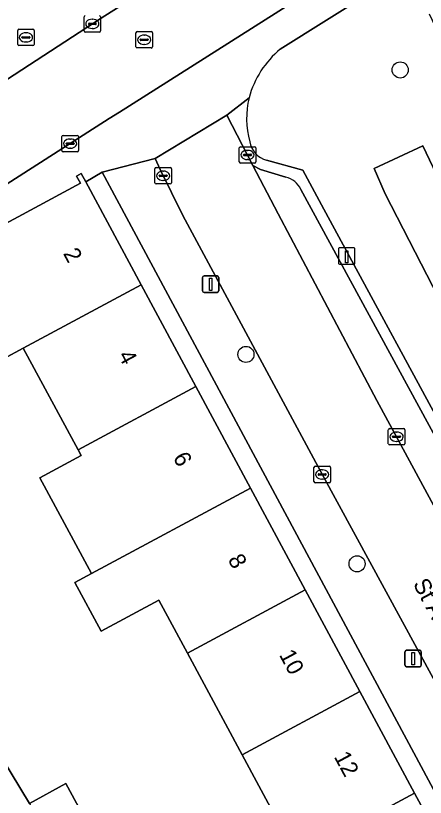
# Model space of a CAD drawing. Extents: x 162523 to 163266, y 381230 to 382050.
# Drawn here: x 162740.82 to 162765.64, y 381862.71 to 381910.12 of the extents above; entities that cross this region are included whole.
import ezdxf

# ---------------------------------------------------------------- set-up
doc = ezdxf.new("R2010")
doc.units = 0
for name, color, linetype in [('IMGEO_Boom', 7, 'Continuous'), ('IMGEO_Brandkraan', 7, 'Continuous'), ('IMGEO_Erf', 7, 'Continuous'), ('IMGEO_Groenvoorziening', 7, 'Continuous'), ('IMGEO_Kolk', 7, 'Continuous'), ('IMGEO_Laadpaal', 7, 'Continuous'), ('IMGEO_Lichtmast', 7, 'Continuous'), ('IMGEO_Openbare_ruimte_label', 7, 'Continuous'), ('IMGEO_Pand', 7, 'Continuous'), ('IMGEO_Pand_nummerreeks', 7, 'Continuous'), ('IMGEO_Parkeervlak_open', 7, 'Continuous'), ('IMGEO_Rijbaan_lokaal_open', 7, 'Continuous'), ('IMGEO_Rioolput', 7, 'Continuous'), ('IMGEO_Voetpad_gesloten', 7, 'Continuous'), ('IMGEO_Voetpad_open', 7, 'Continuous')]:
    doc.layers.add(name, color=color, linetype=linetype)

msp = doc.modelspace()

# ---------------------------------------------------------------- linework, layer by layer
at = {"layer": 'IMGEO_Boom'}
for centre in [(162764.122, 381906.826), (162754.771, 381889.574), (162761.508, 381876.876)]:
    msp.add_circle(centre, 0.489, dxfattribs=at)
at = {"layer": 'IMGEO_Brandkraan'}
for p, q in [((162740.939, 381908.375), (162740.939, 381909.227)), ((162741.014, 381909.301), (162741.866, 381909.301)), ((162741.427, 381909.081), (162741.452, 381909.081)), ((162741.94, 381909.227), (162741.94, 381908.375)), ((162741.198, 381908.795), (162741.198, 381908.807)), ((162741.636, 381908.758), (162741.238, 381908.758)), ((162741.241, 381908.844), (162741.639, 381908.844)), ((162741.45, 381908.521), (162741.425, 381908.521)), ((162741.682, 381908.807), (162741.682, 381908.795)), ((162741.866, 381908.301), (162741.014, 381908.301))]:
    msp.add_line(p, q, dxfattribs=at)
for points in [[(162740.939, 381908.375), (162740.939, 381909.227)], [(162741.014, 381909.301), (162741.866, 381909.301)], [(162741.94, 381909.227), (162741.94, 381908.375)], [(162741.866, 381908.301), (162741.014, 381908.301)]]:
    msp.add_lwpolyline(points, dxfattribs=at)
for centre, radius, start, end in [((162741.016, 381909.225), 0.0765, 91.552, 178.448), ((162741.016, 381909.225), 0.0765, 91.552, 178.448), ((162741.864, 381909.225), 0.0765, 1.552, 88.448), ((162741.864, 381909.225), 0.0765, 1.552, 88.448), ((162741.238, 381908.804), 0.0403, 85.8775, 175.7526), ((162741.235, 381908.794), 0.0366, 178.938, 274.7102), ((162741.639, 381908.801), 0.043, 264.8664, 352.4533), ((162741.643, 381908.806), 0.0386, 1.7309, 96.639), ((162741.016, 381908.377), 0.0765, 181.552, 268.448), ((162741.016, 381908.377), 0.0765, 181.552, 268.448), ((162741.864, 381908.377), 0.0765, 271.552, 358.448), ((162741.864, 381908.377), 0.0765, 271.552, 358.448)]:
    msp.add_arc(centre, radius, start, end, dxfattribs=at)
for centre, major_axis, ratio, start_param, end_param in [((162741.426, 381908.801), (-0.387, 0.002), 0.722429, 4.712389, 7.853982), ((162741.451, 381908.801), (-0.39, 0.002), 0.717154, 1.570796, 4.712389)]:
    msp.add_ellipse(centre, major_axis=major_axis, ratio=ratio, start_param=start_param, end_param=end_param, dxfattribs=at)
at = {"layer": 'IMGEO_Erf'}
msp.add_lwpolyline([(162745.066, 381900.034), (162748.419, 381893.798), (162751.735, 381887.632), (162755.05, 381881.467), (162758.365, 381875.302), (162761.68, 381869.137), (162764.996, 381862.972), (162768.311, 381856.807), (162771.626, 381850.642), (162774.941, 381844.476), (162778.257, 381838.311), (162781.572, 381832.146), (162784.887, 381825.982), (162788.202, 381819.816), (162791.67, 381813.368), (162792.763, 381813.94), (162777.492, 381842.022), (162746.054, 381900.628)], close=True, dxfattribs=at)
msp.add_lwpolyline([(162757.857, 381859.135), (162754.542, 381865.3), (162751.226, 381871.465), (162749.501, 381874.674), (162745.998, 381872.79), (162744.408, 381875.746), (162745.415, 381876.288), (162742.291, 381882.096), (162744.788, 381883.439), (162744.596, 381883.796), (162741.28, 381889.961), (162738.872, 381888.666), (162735.626, 381894.706), (162728.869, 381890.045), (162730.638, 381887.218), (162727.784, 381885.433), (162729.455, 381882.762), (162731.926, 381884.308), (162733.354, 381881.705), (162735.225, 381878.293), (162732.802, 381876.964), (162741.663, 381862.35), (162743.847, 381863.545), (162745.536, 381860.46)], dxfattribs=at)
at = {"layer": 'IMGEO_Groenvoorziening'}
for points in [[(162762.462, 381911.617), (162756.853, 381908.091)], [(162756.019, 381901.355), (162758.227, 381900.744), (162759.496, 381898.373), (162768.087, 381882.528), (162776.948, 381886.694), (162771.409, 381898.579), (162765.889, 381910.215)]]:
    msp.add_lwpolyline(points, dxfattribs=at)
for points in [[(162767.915, 381890.155), (162771.041, 381891.621), (162766.734, 381899.634), (162765.498, 381902.226), (162762.536, 381900.85), (162763.217, 381899.313)], [(162765.498, 381902.226), (162766.734, 381899.634), (162771.041, 381891.621), (162767.915, 381890.155), (162763.217, 381899.313), (162762.536, 381900.85)]]:
    msp.add_lwpolyline(points, close=True, dxfattribs=at)
for centre, radius, start, end in [((162760.626, 381903.59), 5.874, 129.9718, 164.6541), ((162760.088, 381903.884), 5.278, 166.191, 195.4833), ((162756.365, 381902.692), 1.381, 189.0384, 255.4988)]:
    msp.add_arc(centre, radius, start, end, dxfattribs=at)
at = {"layer": 'IMGEO_Kolk'}
for p, q in [((162744.962, 381909.193), (162744.962, 381910.045)), ((162745.963, 381910.045), (162745.963, 381909.193)), ((162745.221, 381909.613), (162745.221, 381909.625)), ((162745.659, 381909.576), (162745.261, 381909.576)), ((162745.264, 381909.662), (162745.662, 381909.662)), ((162745.45, 381909.899), (162745.475, 381909.899)), ((162745.705, 381909.625), (162745.705, 381909.613)), ((162745.889, 381909.119), (162745.037, 381909.119)), ((162745.473, 381909.339), (162745.448, 381909.339)), ((162743.694, 381902.857), (162744.546, 381902.857)), ((162743.619, 381901.931), (162743.619, 381902.783)), ((162743.878, 381902.351), (162743.878, 381902.363)), ((162743.921, 381902.4), (162744.319, 381902.4)), ((162744.107, 381902.637), (162744.132, 381902.637)), ((162744.362, 381902.363), (162744.362, 381902.351)), ((162744.62, 381902.783), (162744.62, 381901.931)), ((162744.546, 381901.857), (162743.694, 381901.857)), ((162744.316, 381902.314), (162743.918, 381902.314)), ((162744.13, 381902.077), (162744.105, 381902.077)), ((162754.369, 381901.244), (162754.369, 381902.096)), ((162754.444, 381902.17), (162755.296, 381902.17)), ((162754.857, 381901.95), (162754.882, 381901.95)), ((162755.37, 381902.096), (162755.37, 381901.244)), ((162754.628, 381901.664), (162754.628, 381901.676)), ((162755.066, 381901.627), (162754.668, 381901.627)), ((162754.671, 381901.713), (162755.069, 381901.713)), ((162754.88, 381901.39), (162754.855, 381901.39)), ((162755.112, 381901.676), (162755.112, 381901.664)), ((162749.331, 381900.91), (162750.183, 381900.91)), ((162755.296, 381901.17), (162754.444, 381901.17)), ((162749.256, 381899.984), (162749.256, 381900.836)), ((162749.558, 381900.453), (162749.956, 381900.453)), ((162749.744, 381900.69), (162749.769, 381900.69)), ((162750.257, 381900.836), (162750.257, 381899.984)), ((162749.515, 381900.404), (162749.515, 381900.416)), ((162749.953, 381900.367), (162749.555, 381900.367)), ((162749.767, 381900.13), (162749.742, 381900.13)), ((162749.999, 381900.416), (162749.999, 381900.404)), ((162750.183, 381899.91), (162749.331, 381899.91)), ((162763.401, 381884.156), (162763.401, 381885.008)), ((162763.476, 381885.082), (162764.328, 381885.082)), ((162763.889, 381884.862), (162763.914, 381884.862)), ((162764.402, 381885.008), (162764.402, 381884.156)), ((162763.66, 381884.576), (162763.66, 381884.588)), ((162764.098, 381884.539), (162763.7, 381884.539)), ((162763.703, 381884.625), (162764.101, 381884.625)), ((162764.144, 381884.588), (162764.144, 381884.576)), ((162764.328, 381884.082), (162763.476, 381884.082)), ((162763.912, 381884.302), (162763.887, 381884.302)), ((162758.894, 381881.869), (162758.894, 381882.721)), ((162758.969, 381882.795), (162759.821, 381882.795)), ((162759.382, 381882.575), (162759.407, 381882.575)), ((162759.895, 381882.721), (162759.895, 381881.869)), ((162759.153, 381882.289), (162759.153, 381882.301)), ((162759.591, 381882.252), (162759.193, 381882.252)), ((162759.196, 381882.338), (162759.594, 381882.338)), ((162759.405, 381882.015), (162759.38, 381882.015)), ((162759.637, 381882.301), (162759.637, 381882.289)), ((162759.821, 381881.795), (162758.969, 381881.795))]:
    msp.add_line(p, q, dxfattribs=at)
for points in [[(162744.962, 381909.193), (162744.962, 381910.045)], [(162745.963, 381910.045), (162745.963, 381909.193)], [(162745.889, 381909.119), (162745.037, 381909.119)], [(162743.694, 381902.857), (162744.546, 381902.857)], [(162743.619, 381901.931), (162743.619, 381902.783)], [(162744.62, 381902.783), (162744.62, 381901.931)], [(162744.546, 381901.857), (162743.694, 381901.857)], [(162754.369, 381901.244), (162754.369, 381902.096)], [(162754.444, 381902.17), (162755.296, 381902.17)], [(162755.37, 381902.096), (162755.37, 381901.244)], [(162749.331, 381900.91), (162750.183, 381900.91)], [(162755.296, 381901.17), (162754.444, 381901.17)], [(162749.256, 381899.984), (162749.256, 381900.836)], [(162750.257, 381900.836), (162750.257, 381899.984)], [(162750.183, 381899.91), (162749.331, 381899.91)], [(162763.401, 381884.156), (162763.401, 381885.008)], [(162763.476, 381885.082), (162764.328, 381885.082)], [(162764.402, 381885.008), (162764.402, 381884.156)], [(162764.328, 381884.082), (162763.476, 381884.082)], [(162758.894, 381881.869), (162758.894, 381882.721)], [(162758.969, 381882.795), (162759.821, 381882.795)], [(162759.895, 381882.721), (162759.895, 381881.869)], [(162759.821, 381881.795), (162758.969, 381881.795)]]:
    msp.add_lwpolyline(points, dxfattribs=at)
for centre, radius, start, end in [((162745.039, 381910.043), 0.0765, 91.552, 178.448), ((162745.039, 381910.043), 0.0765, 91.552, 178.448), ((162745.887, 381910.043), 0.0765, 1.552, 88.448), ((162745.887, 381910.043), 0.0765, 1.552, 88.448), ((162745.261, 381909.622), 0.0403, 85.8775, 175.7526), ((162745.258, 381909.612), 0.0366, 178.938, 274.7102), ((162745.662, 381909.619), 0.043, 264.8664, 352.4533), ((162745.666, 381909.624), 0.0386, 1.7309, 96.639), ((162745.039, 381909.195), 0.0765, 181.552, 268.448), ((162745.039, 381909.195), 0.0765, 181.552, 268.448), ((162745.887, 381909.195), 0.0765, 271.552, 358.448), ((162745.887, 381909.195), 0.0765, 271.552, 358.448), ((162743.696, 381902.781), 0.0765, 91.552, 178.448), ((162743.696, 381902.781), 0.0765, 91.552, 178.448), ((162744.544, 381902.781), 0.0765, 1.552, 88.448), ((162744.544, 381902.781), 0.0765, 1.552, 88.448), ((162743.918, 381902.36), 0.0403, 85.8775, 175.7526), ((162743.915, 381902.35), 0.0366, 178.938, 274.7102), ((162744.319, 381902.357), 0.043, 264.8664, 352.4533), ((162744.323, 381902.362), 0.0386, 1.7309, 96.639), ((162743.696, 381901.933), 0.0765, 181.552, 268.448), ((162743.696, 381901.933), 0.0765, 181.552, 268.448), ((162744.544, 381901.933), 0.0765, 271.552, 358.448), ((162744.544, 381901.933), 0.0765, 271.552, 358.448), ((162754.446, 381902.094), 0.0765, 91.552, 178.448), ((162754.446, 381902.094), 0.0765, 91.552, 178.448), ((162755.294, 381902.094), 0.0765, 1.552, 88.448), ((162755.294, 381902.094), 0.0765, 1.552, 88.448), ((162754.668, 381901.673), 0.0403, 85.8775, 175.7526), ((162754.665, 381901.663), 0.0366, 178.938, 274.7102), ((162755.069, 381901.67), 0.043, 264.8664, 352.4533), ((162755.073, 381901.675), 0.0386, 1.7309, 96.639), ((162749.333, 381900.834), 0.0765, 91.552, 178.448), ((162749.333, 381900.834), 0.0765, 91.552, 178.448), ((162750.181, 381900.834), 0.0765, 1.552, 88.448), ((162750.181, 381900.834), 0.0765, 1.552, 88.448), ((162754.446, 381901.246), 0.0765, 181.552, 268.448), ((162754.446, 381901.246), 0.0765, 181.552, 268.448), ((162755.294, 381901.246), 0.0765, 271.552, 358.448), ((162755.294, 381901.246), 0.0765, 271.552, 358.448), ((162749.555, 381900.413), 0.0403, 85.8775, 175.7526), ((162749.96, 381900.415), 0.0386, 1.7309, 96.639), ((162749.333, 381899.986), 0.0765, 181.552, 268.448), ((162749.333, 381899.986), 0.0765, 181.552, 268.448), ((162749.552, 381900.403), 0.0366, 178.938, 274.7102), ((162749.956, 381900.41), 0.043, 264.8664, 352.4533), ((162750.181, 381899.986), 0.0765, 271.552, 358.448), ((162750.181, 381899.986), 0.0765, 271.552, 358.448), ((162763.478, 381885.006), 0.0765, 91.552, 178.448), ((162763.478, 381885.006), 0.0765, 91.552, 178.448), ((162764.326, 381885.006), 0.0765, 1.552, 88.448), ((162764.326, 381885.006), 0.0765, 1.552, 88.448), ((162763.7, 381884.585), 0.0403, 85.8775, 175.7526), ((162763.697, 381884.575), 0.0366, 178.938, 274.7102), ((162764.101, 381884.582), 0.043, 264.8664, 352.4533), ((162764.105, 381884.587), 0.0386, 1.7309, 96.639), ((162763.478, 381884.158), 0.0765, 181.552, 268.448), ((162763.478, 381884.158), 0.0765, 181.552, 268.448), ((162764.326, 381884.158), 0.0765, 271.552, 358.448), ((162764.326, 381884.158), 0.0765, 271.552, 358.448), ((162758.971, 381882.719), 0.0765, 91.552, 178.448), ((162758.971, 381882.719), 0.0765, 91.552, 178.448), ((162759.819, 381882.719), 0.0765, 1.552, 88.448), ((162759.819, 381882.719), 0.0765, 1.552, 88.448), ((162759.193, 381882.298), 0.0403, 85.8775, 175.7526), ((162759.19, 381882.288), 0.0366, 178.938, 274.7102), ((162759.594, 381882.295), 0.043, 264.8664, 352.4533), ((162759.598, 381882.3), 0.0386, 1.7309, 96.639), ((162758.971, 381881.871), 0.0765, 181.552, 268.448), ((162758.971, 381881.871), 0.0765, 181.552, 268.448), ((162759.819, 381881.871), 0.0765, 271.552, 358.448), ((162759.819, 381881.871), 0.0765, 271.552, 358.448)]:
    msp.add_arc(centre, radius, start, end, dxfattribs=at)
for centre, major_axis, ratio, start_param, end_param in [((162745.449, 381909.619), (-0.387, 0.002), 0.722429, 4.712389, 7.853982), ((162745.474, 381909.619), (-0.39, 0.002), 0.717154, 1.570796, 4.712389), ((162744.106, 381902.357), (-0.387, 0.002), 0.722429, 4.712389, 7.853982), ((162744.131, 381902.357), (-0.39, 0.002), 0.717154, 1.570796, 4.712389), ((162754.856, 381901.67), (-0.387, 0.002), 0.722429, 4.712389, 7.853982), ((162754.881, 381901.67), (-0.39, 0.002), 0.717154, 1.570796, 4.712389), ((162749.743, 381900.41), (-0.387, 0.002), 0.722429, 4.712389, 7.853982), ((162749.768, 381900.41), (-0.39, 0.002), 0.717154, 1.570796, 4.712389), ((162763.888, 381884.582), (-0.387, 0.002), 0.722429, 4.712389, 7.853982), ((162763.913, 381884.582), (-0.39, 0.002), 0.717154, 1.570796, 4.712389), ((162759.381, 381882.295), (-0.387, 0.002), 0.722429, 4.712389, 7.853982), ((162759.406, 381882.295), (-0.39, 0.002), 0.717154, 1.570796, 4.712389)]:
    msp.add_ellipse(centre, major_axis=major_axis, ratio=ratio, start_param=start_param, end_param=end_param, dxfattribs=at)
at = {"layer": 'IMGEO_Laadpaal'}
for p, q in [((162760.381, 381895.961), (162760.381, 381895.12)), ((162760.381, 381895.961), (162760.381, 381895.12)), ((162761.297, 381896.045), (162760.456, 381896.045)), ((162761.297, 381896.045), (162760.456, 381896.045)), ((162761.381, 381895.129), (162761.381, 381895.97)), ((162761.381, 381895.129), (162761.381, 381895.97)), ((162760.465, 381895.045), (162761.306, 381895.045)), ((162760.465, 381895.045), (162761.306, 381895.045))]:
    msp.add_line(p, q, dxfattribs=at)
msp.add_lwpolyline([(162760.796, 381895.858), (162760.956, 381895.858), (162760.956, 381895.125), (162760.796, 381895.125), (162760.796, 381895.858)], dxfattribs=at)
for centre, start, end in [((162760.459, 381895.967), 92.4484, 184.2845), ((162760.459, 381895.967), 92.4484, 184.2845), ((162761.303, 381895.967), 2.4484, 94.2845), ((162761.303, 381895.967), 2.4484, 94.2845), ((162760.459, 381895.123), 182.4484, 274.2845), ((162760.459, 381895.123), 182.4484, 274.2845), ((162761.303, 381895.123), 272.4484, 4.2845), ((162761.303, 381895.123), 272.4484, 4.2845)]:
    msp.add_arc(centre, 0.0779, start, end, dxfattribs=at)
at = {"layer": 'IMGEO_Lichtmast'}
for p, q in [((162752.237, 381894.332), (162753.027, 381894.332)), ((162753.027, 381894.332), (162752.237, 381894.332)), ((162752.137, 381893.432), (162752.137, 381894.232)), ((162752.137, 381894.232), (162752.137, 381893.432)), ((162753.127, 381894.232), (162753.127, 381893.432)), ((162753.127, 381893.432), (162753.127, 381894.232)), ((162753.027, 381893.332), (162752.237, 381893.332)), ((162752.237, 381893.332), (162753.027, 381893.332)), ((162764.411, 381870.73), (162764.411, 381871.53)), ((162764.411, 381871.53), (162764.411, 381870.73)), ((162764.511, 381871.63), (162765.301, 381871.63)), ((162765.301, 381871.63), (162764.511, 381871.63)), ((162765.401, 381871.53), (162765.401, 381870.73)), ((162765.401, 381870.73), (162765.401, 381871.53)), ((162765.301, 381870.63), (162764.511, 381870.63)), ((162764.511, 381870.63), (162765.301, 381870.63))]:
    msp.add_line(p, q, dxfattribs=at)
for points in [[(162752.557, 381894.207), (162752.707, 381894.207), (162752.707, 381893.457), (162752.557, 381893.457), (162752.557, 381894.207)], [(162764.831, 381871.505), (162764.981, 381871.505), (162764.981, 381870.755), (162764.831, 381870.755), (162764.831, 381871.505)]]:
    msp.add_lwpolyline(points, dxfattribs=at)
for centre, start, end in [((162752.237, 381894.232), 90, 180), ((162752.237, 381894.232), 90, 180), ((162753.027, 381894.232), 0, 90), ((162753.027, 381894.232), 360, 90), ((162752.237, 381893.432), 180, 270), ((162752.237, 381893.432), 180, 270), ((162753.027, 381893.432), 270, 0), ((162753.027, 381893.432), 270, 0), ((162764.511, 381871.53), 90, 180), ((162764.511, 381871.53), 90, 180), ((162765.301, 381871.53), 0, 90), ((162765.301, 381871.53), 360, 90), ((162764.511, 381870.73), 180, 270), ((162764.511, 381870.73), 180, 270), ((162765.301, 381870.73), 270, 0), ((162765.301, 381870.73), 270, 0)]:
    msp.add_arc(centre, 0.1, start, end, dxfattribs=at)
at = {"layer": 'IMGEO_Pand'}
for points in [[(162748.419, 381893.798), (162745.066, 381900.034), (162744.791, 381900.545), (162744.509, 381900.392), (162744.745, 381899.951), (162738.173, 381896.419), (162737.936, 381896.86), (162737.654, 381896.708), (162737.89, 381896.267), (162735.626, 381894.706), (162738.872, 381888.666), (162741.28, 381889.961)], [(162751.735, 381887.632), (162748.419, 381893.798), (162741.28, 381889.961), (162744.596, 381883.796)], [(162751.735, 381887.632), (162744.596, 381883.796), (162744.788, 381883.439), (162742.291, 381882.096), (162745.415, 381876.288), (162755.05, 381881.467)], [(162755.05, 381881.467), (162745.415, 381876.288), (162744.408, 381875.746), (162745.998, 381872.79), (162749.501, 381874.674), (162751.226, 381871.465), (162758.365, 381875.302)], [(162751.226, 381871.465), (162754.542, 381865.3), (162761.68, 381869.137), (162758.365, 381875.302)], [(162761.68, 381869.137), (162754.542, 381865.3), (162757.857, 381859.135), (162764.996, 381862.972)], [(162745.536, 381860.46), (162743.847, 381863.545), (162741.663, 381862.35), (162743.343, 381859.281)], [(162761.172, 381852.97), (162768.311, 381856.807), (162764.996, 381862.972), (162757.857, 381859.135)]]:
    msp.add_lwpolyline(points, close=True, dxfattribs=at)
at = {"layer": 'IMGEO_Parkeervlak_open'}
for points in [[(162757.187, 381900.322), (162755.652, 381900.795), (162755.199, 381901.032), (162756.718, 381898.098), (162762.713, 381886.779), (162770.784, 381871.85), (162778.787, 381857.004), (162784.378, 381846.682), (162792.865, 381830.868), (162802.661, 381812.802)], [(162775.404, 381867.717), (162758.099, 381899.571)]]:
    msp.add_lwpolyline(points, dxfattribs=at)
msp.add_arc((162756.906, 381899.051), 1.302, 23.5438, 77.5157, dxfattribs=at)
at = {"layer": 'IMGEO_Rijbaan_lokaal_open'}
for points in [[(162728.092, 381892.085), (162733.021, 381895.276), (162746.493, 381903.872), (162747.117, 381904.27), (162753.065, 381908.037), (162757.37, 381910.766), (162754.588, 381915.413), (162753.541, 381914.762), (162746.002, 381909.969), (162731.552, 381900.569), (162716.347, 381890.607), (162712.639, 381888.043), (162710.772, 381886.8), (162705.831, 381883.214), (162702.789, 381880.999), (162700.595, 381879.197), (162704.065, 381874.976), (162707.792, 381878.046), (162710.957, 381880.489), (162714.111, 381882.861), (162715.828, 381884.045), (162719.862, 381886.809), (162723.541, 381889.18), (162724.903, 381890.021)], [(162778.787, 381857.004), (162770.784, 381871.85), (162762.713, 381886.779), (162756.718, 381898.098), (162755.199, 381901.032), (162753.623, 381904.075), (162749.263, 381901.449), (162749.572, 381900.789), (162750.943, 381898.002), (162759.427, 381882.237), (162768.958, 381864.708), (162772.767, 381857.443), (162784.611, 381835.53), (162799.119, 381808.655), (162803.612, 381811.049), (162803.17, 381811.863), (162802.661, 381812.802), (162792.865, 381830.868), (162784.378, 381846.682)]]:
    msp.add_lwpolyline(points, close=True, dxfattribs=at)
at = {"layer": 'IMGEO_Rioolput'}
for p, q in [((162748.108, 381908.231), (162748.108, 381909.083)), ((162748.183, 381909.157), (162749.035, 381909.157)), ((162749.109, 381909.083), (162749.109, 381908.231)), ((162748.367, 381908.651), (162748.367, 381908.663)), ((162748.805, 381908.614), (162748.407, 381908.614)), ((162748.41, 381908.7), (162748.808, 381908.7)), ((162748.596, 381908.937), (162748.621, 381908.937)), ((162748.851, 381908.663), (162748.851, 381908.651)), ((162749.035, 381908.157), (162748.183, 381908.157)), ((162748.619, 381908.377), (162748.594, 381908.377))]:
    msp.add_line(p, q, dxfattribs=at)
for points in [[(162748.108, 381908.231), (162748.108, 381909.083)], [(162748.183, 381909.157), (162749.035, 381909.157)], [(162749.109, 381909.083), (162749.109, 381908.231)], [(162749.035, 381908.157), (162748.183, 381908.157)]]:
    msp.add_lwpolyline(points, dxfattribs=at)
for centre, radius, start, end in [((162748.185, 381909.081), 0.0765, 91.552, 178.448), ((162748.185, 381909.081), 0.0765, 91.552, 178.448), ((162749.033, 381909.081), 0.0765, 1.552, 88.448), ((162749.033, 381909.081), 0.0765, 1.552, 88.448), ((162748.407, 381908.66), 0.0403, 85.8775, 175.7526), ((162748.404, 381908.65), 0.0366, 178.938, 274.7102), ((162748.808, 381908.657), 0.043, 264.8664, 352.4533), ((162748.812, 381908.662), 0.0386, 1.7309, 96.639), ((162748.185, 381908.233), 0.0765, 181.552, 268.448), ((162748.185, 381908.233), 0.0765, 181.552, 268.448), ((162749.033, 381908.233), 0.0765, 271.552, 358.448), ((162749.033, 381908.233), 0.0765, 271.552, 358.448)]:
    msp.add_arc(centre, radius, start, end, dxfattribs=at)
for centre, major_axis, ratio, start_param, end_param in [((162748.595, 381908.657), (-0.387, 0.002), 0.722429, 4.712389, 7.853982), ((162748.62, 381908.657), (-0.39, 0.002), 0.717154, 1.570796, 4.712389)]:
    msp.add_ellipse(centre, major_axis=major_axis, ratio=ratio, start_param=start_param, end_param=end_param, dxfattribs=at)
at = {"layer": 'IMGEO_Voetpad_gesloten'}
msp.add_lwpolyline([(162672.848, 381856.46), (162681.316, 381863.363), (162688.855, 381869.619), (162694.996, 381874.59), (162695.513, 381875.009), (162700.595, 381879.197), (162702.789, 381880.999), (162705.831, 381883.214), (162710.772, 381886.8), (162712.639, 381888.043), (162716.347, 381890.607), (162731.552, 381900.569), (162746.002, 381909.969), (162753.541, 381914.762), (162754.588, 381915.413), (162760.8, 381919.183)], dxfattribs=at)
at = {"layer": 'IMGEO_Voetpad_open'}
for points in [[(162765.264, 381915.753), (162763.541, 381914.667), (162760.275, 381912.607), (162757.37, 381910.766), (162753.065, 381908.037), (162747.117, 381904.27), (162746.493, 381903.872), (162733.021, 381895.276), (162728.092, 381892.085), (162724.903, 381890.021), (162723.541, 381889.18), (162719.862, 381886.809), (162715.828, 381884.045), (162714.111, 381882.861), (162710.957, 381880.489), (162707.792, 381878.046), (162704.065, 381874.976), (162702.51, 381873.695), (162698.457, 381870.411), (162695.216, 381867.785)], [(162756.853, 381908.091), (162762.462, 381911.617)], [(162738.173, 381896.419), (162744.745, 381899.951), (162744.509, 381900.392), (162744.791, 381900.545), (162745.066, 381900.034), (162746.054, 381900.628), (162749.263, 381901.449), (162753.623, 381904.075), (162754.962, 381905.144)], [(162754.962, 381905.144), (162753.623, 381904.075), (162755.199, 381901.032), (162755.652, 381900.795), (162757.187, 381900.322)], [(162750.943, 381898.002), (162749.572, 381900.789), (162749.263, 381901.449), (162746.054, 381900.628), (162777.492, 381842.022), (162792.763, 381813.94), (162795.826, 381808.308)], [(162759.496, 381898.373), (162758.227, 381900.744), (162756.019, 381901.355)], [(162758.099, 381899.571), (162775.404, 381867.717), (162802.933, 381816.582)], [(162803.684, 381816.507), (162794.87, 381832.83), (162794.115, 381834.218), (162781.865, 381856.968), (162781.105, 381858.309), (162768.874, 381881.068), (162768.087, 381882.528), (162759.496, 381898.373)], [(162796.115, 381807.158), (162799.119, 381808.655), (162784.611, 381835.53), (162772.767, 381857.443), (162768.958, 381864.708), (162759.427, 381882.237), (162750.943, 381898.002)], [(162741.663, 381862.35), (162732.802, 381876.964), (162732.674, 381876.894), (162730.802, 381880.306), (162729.455, 381882.762), (162727.784, 381885.433), (162726.015, 381888.26), (162724.642, 381887.384), (162726.064, 381885.112), (162728.067, 381881.91), (162729.267, 381879.992), (162731.503, 381875.915), (162733.19, 381873.172), (162733.213, 381873.185), (162733.583, 381872.534), (162736.322, 381867.712), (162738.091, 381864.598), (162738.115, 381864.612), (162752.78, 381839.267)]]:
    msp.add_lwpolyline(points, dxfattribs=at)
for centre, radius, start, end in [((162760.626, 381903.59), 5.874, 129.9718, 164.6541), ((162760.088, 381903.884), 5.278, 166.191, 195.4833), ((162756.365, 381902.692), 1.381, 189.0384, 255.4988), ((162756.906, 381899.051), 1.302, 23.5438, 77.5157)]:
    msp.add_arc(centre, radius, start, end, dxfattribs=at)

# ---------------------------------------------------------------- texts
at = {"layer": 'IMGEO_Openbare_ruimte_label'}
msp.add_text('St Adelbertuslaan', height=1, rotation=297.8973, dxfattribs=at).set_placement((162764.871, 381875.671))
at = {"layer": 'IMGEO_Pand_nummerreeks'}
for s, rotation, p in [('2', 298.2688, (162743.671, 381895.701)), ('4', 298.2688, (162746.999, 381889.514)), ('6', 298.2695, (162750.325, 381883.328)), ('8', 298.2695, (162753.653, 381877.14)), ('10', 298.2688, (162756.76, 381871.361)), ('12', 298.2688, (162760.083, 381865.18))]:
    msp.add_text(s, height=1, rotation=rotation, dxfattribs=at).set_placement(p)

doc.saveas('drawing.dxf')
